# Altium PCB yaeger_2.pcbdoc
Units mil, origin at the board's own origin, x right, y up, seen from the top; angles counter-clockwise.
Board outline 3740.2 x 3149.6 mil, 2 copper layers (Top Layer, Bottom Layer), stack 62.2 mil thick; 33 components, 33 nets, 195 pads, 8 vias.
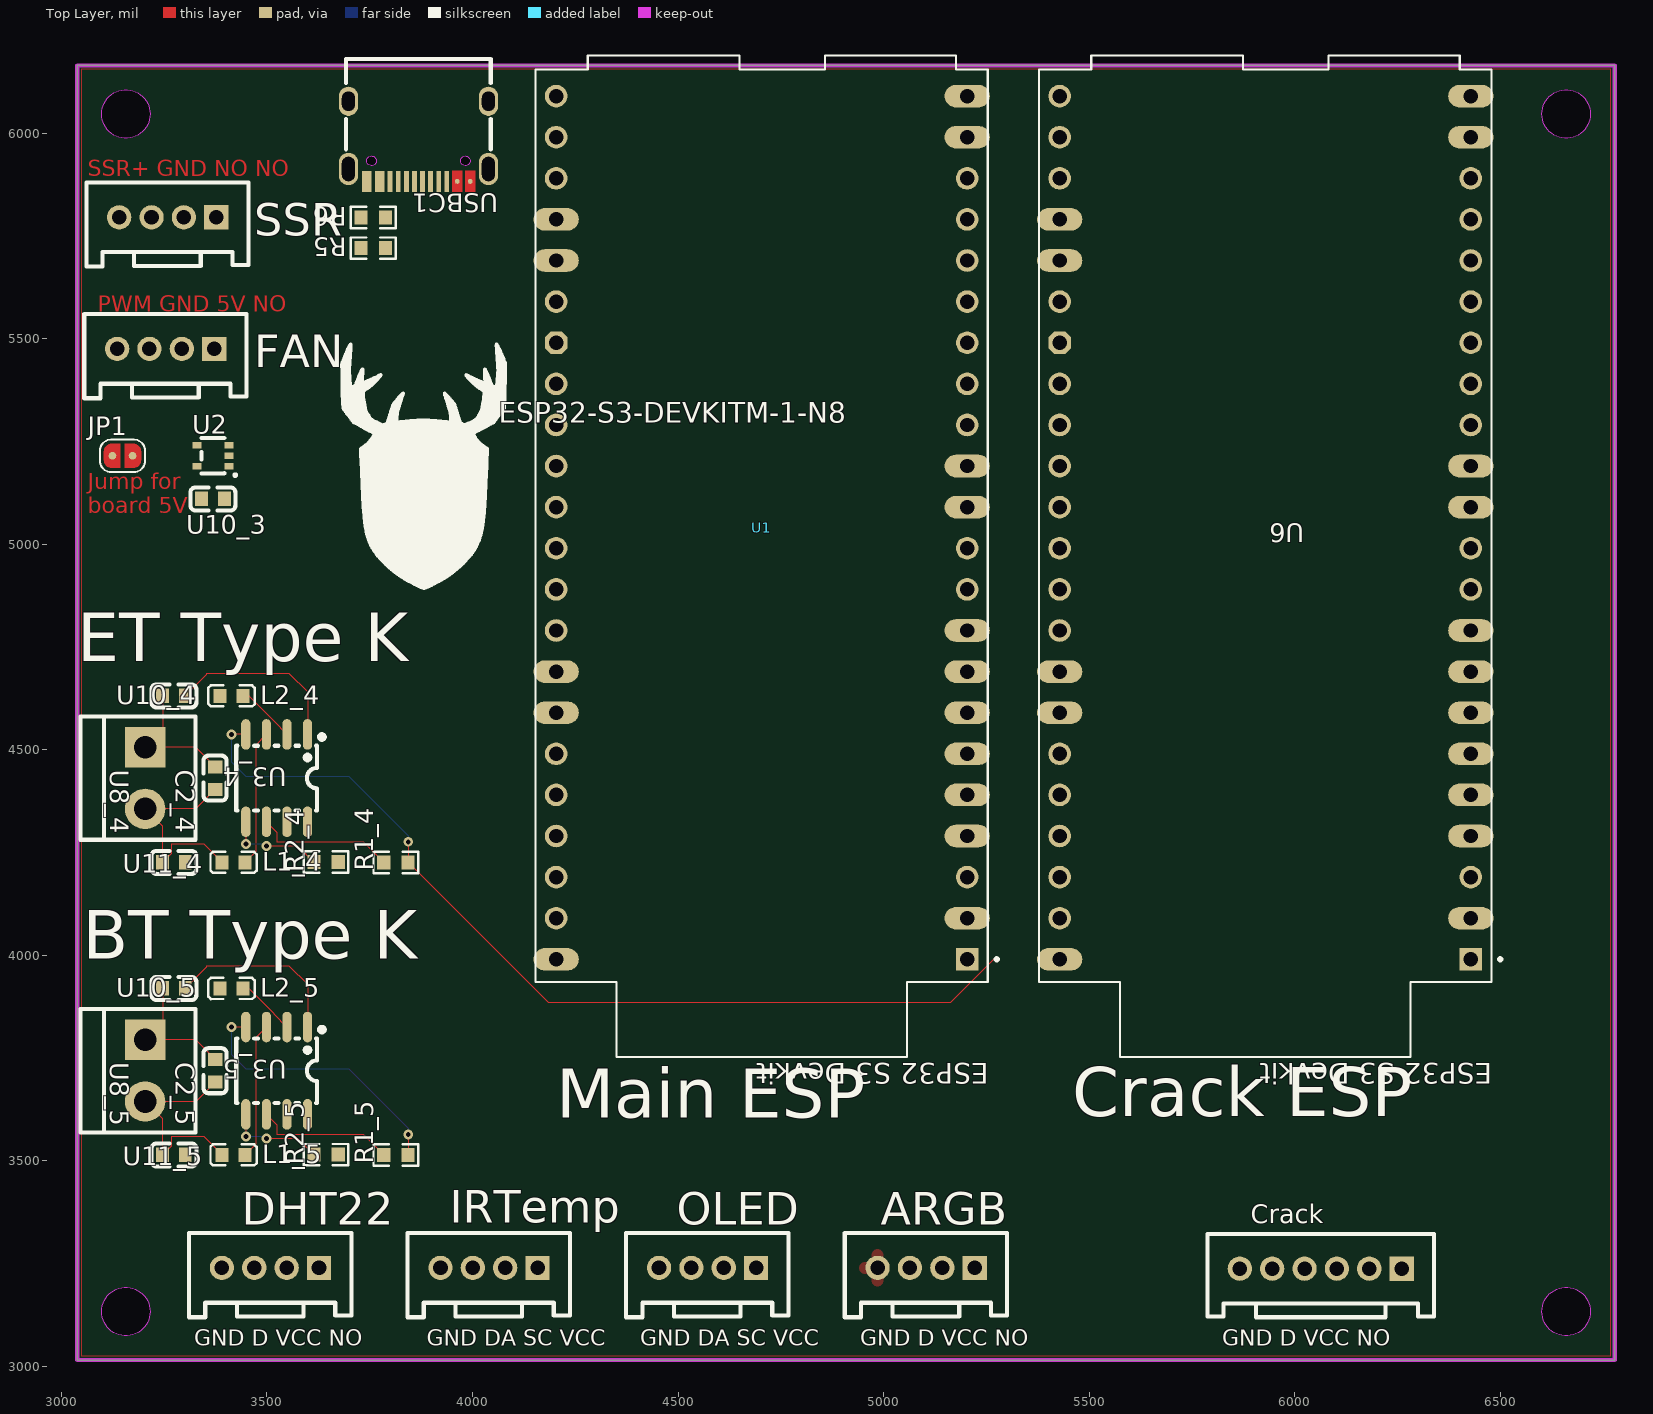
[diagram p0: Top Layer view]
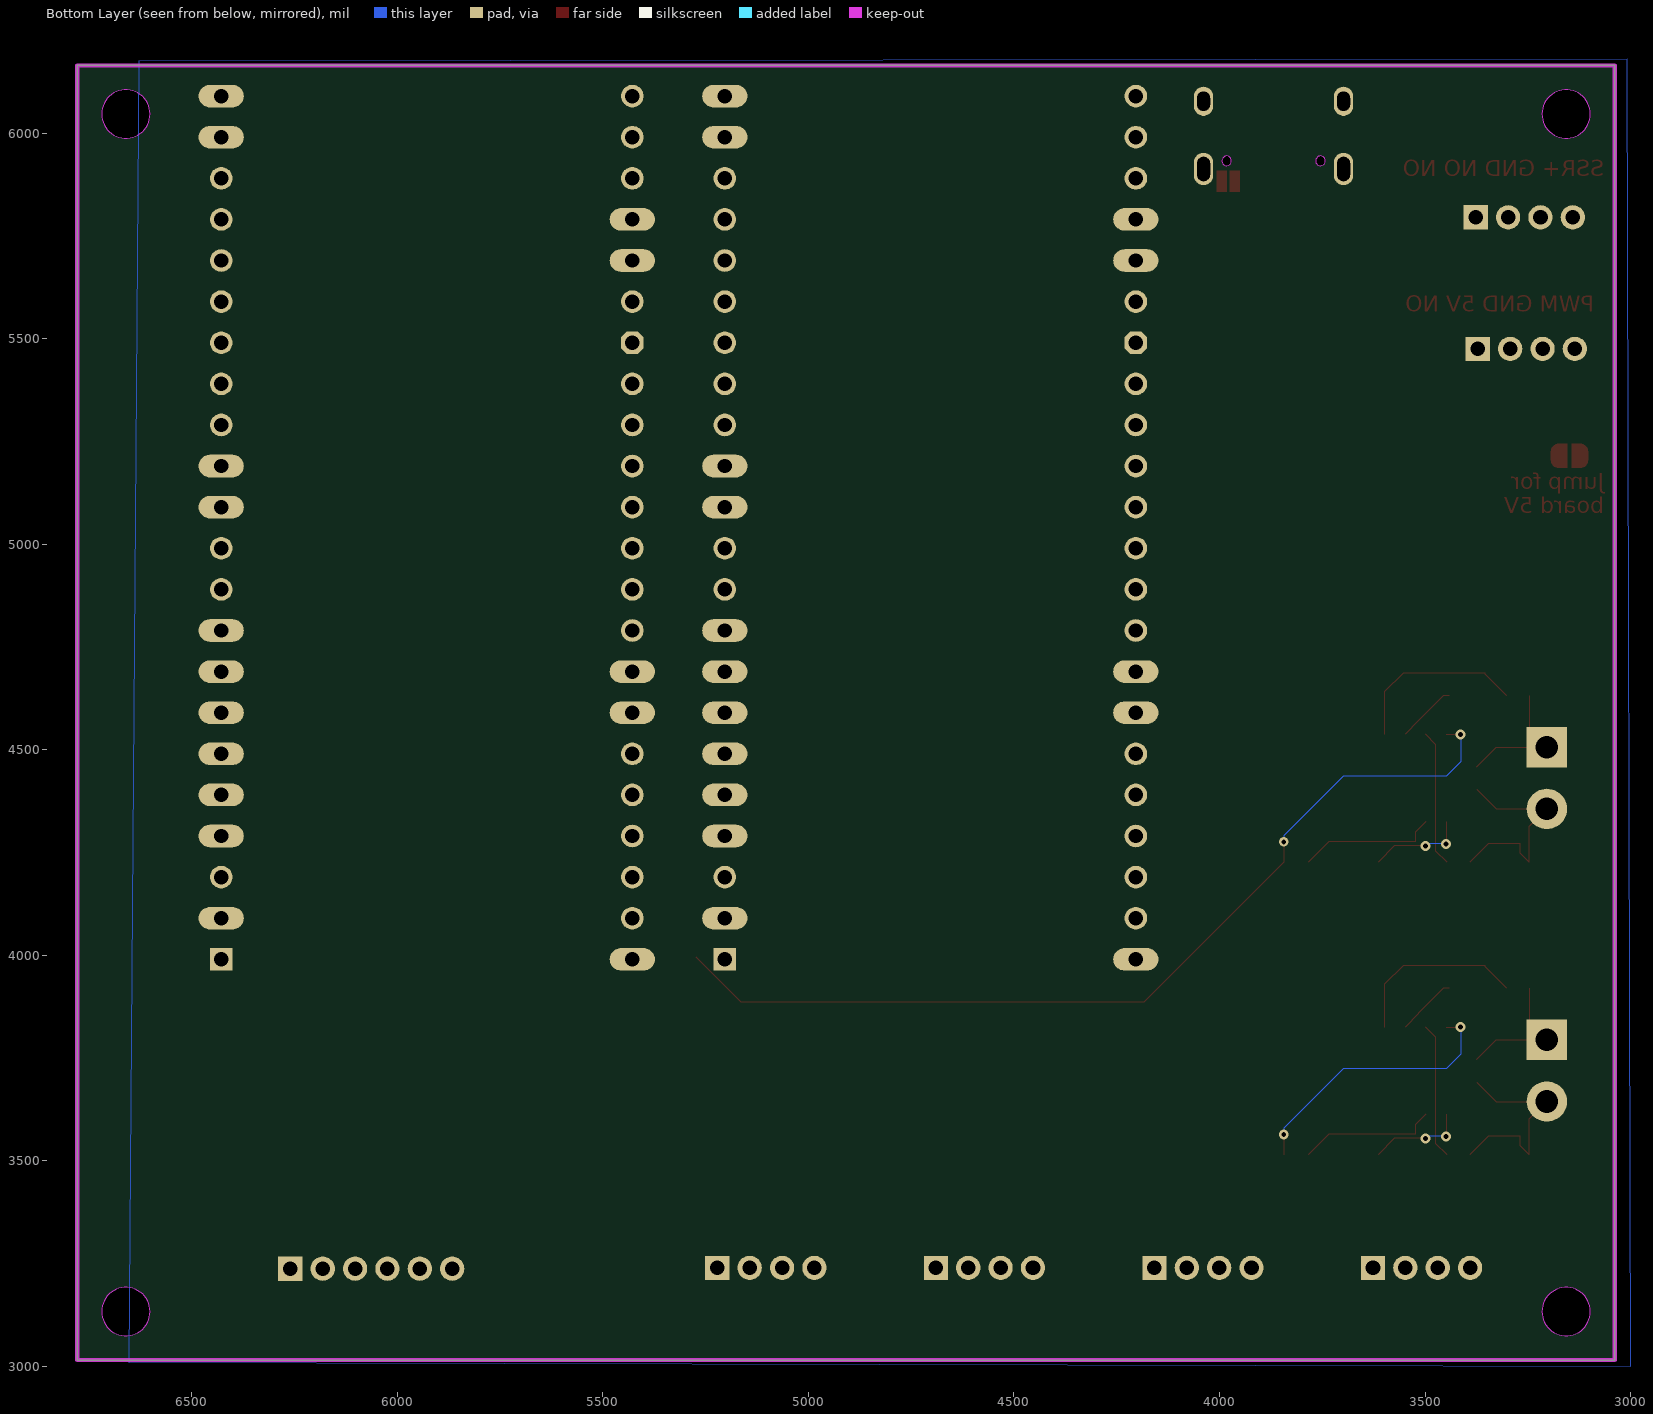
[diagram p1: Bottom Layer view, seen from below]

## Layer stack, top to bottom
Top Solder Mask Layer: solder mask 0.4, Dk 3.3
Top Layer: signal copper 1.4
Dielectric1: surface 59.4, FR4, Dk 4.5
Bottom Layer: signal copper 1.4
Bottom Solder Mask Layer: solder mask 0.4, Dk 3.3

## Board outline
3038.6,6164.7 3038.6,3015.1 6778.8,3015.1 6778.8,6164.7
cut-out: 3215.8,6046.6 3215.4,6039.7 3214.2,6032.9 3212.2,6026.4 3209.5,6020.1 3206.1,6014.1 3202,6008.6 3197.2,6003.6 3192,5999.2 3186.2,5995.4 3180.1,5992.3 3173.6,5990 3167,5988.4 3160.1,5987.6 3153.3,5987.6 3146.5,5988.4 3139.8,5990 3133.3,5992.3 3127.2,5995.4 3121.4,5999.2 3116.2,6003.6 3111.5,6008.6 3107.4,6014.1 3103.9,6020.1 3101.2,6026.4 3099.2,6032.9 3098.1,6039.7 3097.7,6046.6 3098.1,6053.4 3099.2,6060.2 3101.2,6066.8 3103.9,6073.1 3107.4,6079 3111.5,6084.5 3116.2,6089.5 3121.4,6093.9 3127.2,6097.7 3133.3,6100.8 3139.8,6103.1 3146.5,6104.7 3153.3,6105.5 3160.1,6105.5 3167,6104.7 3173.6,6103.1 3180.1,6100.8 3186.2,6097.7 3192,6093.9 3197.2,6089.5 3202,6084.5 3206.1,6079 3209.5,6073.1 3212.2,6066.8 3214.2,6060.2 3215.4,6053.4
cut-out: 6719.7,6046.6 6719.3,6039.7 6718.1,6032.9 6716.1,6026.4 6713.4,6020.1 6710,6014.1 6705.9,6008.6 6701.2,6003.6 6695.9,5999.2 6690.2,5995.4 6684,5992.3 6677.6,5990 6670.9,5988.4 6664.1,5987.6 6657.2,5987.6 6650.4,5988.4 6643.7,5990 6637.3,5992.3 6631.1,5995.4 6625.4,5999.2 6620.1,6003.6 6615.4,6008.6 6611.3,6014.1 6607.9,6020.1 6605.2,6026.4 6603.2,6032.9 6602,6039.7 6601.6,6046.6 6602,6053.4 6603.2,6060.2 6605.2,6066.8 6607.9,6073.1 6611.3,6079 6615.4,6084.5 6620.1,6089.5 6625.4,6093.9 6631.1,6097.7 6637.3,6100.8 6643.7,6103.1 6650.4,6104.7 6657.2,6105.5 6664.1,6105.5 6670.9,6104.7 6677.6,6103.1 6684,6100.8 6690.2,6097.7 6695.9,6093.9 6701.2,6089.5 6705.9,6084.5 6710,6079 6713.4,6073.1 6716.1,6066.8 6718.1,6060.2 6719.3,6053.4
cut-out: 6719.7,3133.2 6719.3,3126.3 6718.1,3119.6 6716.1,3113 6713.4,3106.7 6710,3100.7 6705.9,3095.2 6701.2,3090.2 6695.9,3085.8 6690.2,3082 6684,3078.9 6677.6,3076.6 6670.9,3075 6664.1,3074.2 6657.2,3074.2 6650.4,3075 6643.7,3076.6 6637.3,3078.9 6631.1,3082 6625.4,3085.8 6620.1,3090.2 6615.4,3095.2 6611.3,3100.7 6607.9,3106.7 6605.2,3113 6603.2,3119.6 6602,3126.3 6601.6,3133.2 6602,3140 6603.2,3146.8 6605.2,3153.4 6607.9,3159.7 6611.3,3165.6 6615.4,3171.1 6620.1,3176.1 6625.4,3180.5 6631.1,3184.3 6637.3,3187.4 6643.7,3189.7 6650.4,3191.3 6657.2,3192.1 6664.1,3192.1 6670.9,3191.3 6677.6,3189.7 6684,3187.4 6690.2,3184.3 6695.9,3180.5 6701.2,3176.1 6705.9,3171.1 6710,3165.6 6713.4,3159.7 6716.1,3153.4 6718.1,3146.8 6719.3,3140
cut-out: 3215.8,3133.2 3215.4,3126.3 3214.2,3119.6 3212.2,3113 3209.5,3106.7 3206.1,3100.7 3202,3095.2 3197.2,3090.2 3192,3085.8 3186.2,3082 3180.1,3078.9 3173.6,3076.6 3167,3075 3160.1,3074.2 3153.3,3074.2 3146.5,3075 3139.8,3076.6 3133.3,3078.9 3127.2,3082 3121.4,3085.8 3116.2,3090.2 3111.5,3095.2 3107.4,3100.7 3103.9,3106.7 3101.2,3113 3099.2,3119.6 3098.1,3126.3 3097.7,3133.2 3098.1,3140 3099.2,3146.8 3101.2,3153.4 3103.9,3159.7 3107.4,3165.6 3111.5,3171.1 3116.2,3176.1 3121.4,3180.5 3127.2,3184.3 3133.3,3187.4 3139.8,3189.7 3146.5,3191.3 3153.3,3192.1 3160.1,3192.1 3167,3191.3 3173.6,3189.7 3180.1,3187.4 3186.2,3184.3 3192,3180.5 3197.2,3176.1 3202,3171.1 3206.1,3165.6 3209.5,3159.7 3212.2,3153.4 3214.2,3146.8 3215.4,3140

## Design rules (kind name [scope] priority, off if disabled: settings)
BoardOutlineClearance safeClearance [All] p0: genericclearance=10 ignorepadtopadclearanceinfootprint=FALSE except(0: Arc-SplitContinuation Track-SplitContinuation SMDPad-SplitContinuation THPad-SplitContinuation Via-SplitContinuation Fill-SplitContinuation Poly-SplitContinuation Region-SplitContinuation Text-SplitContinuation)
BoardOutlineClearance Plane_innerPlane [All] p0: genericclearance=10 ignorepadtopadclearanceinfootprint=FALSE except(0: Arc-SplitContinuation Track-SplitContinuation SMDPad-SplitContinuation THPad-SplitContinuation Via-SplitContinuation Fill-SplitContinuation Poly-SplitContinuation Region-SplitContinuation Text-SplitContinuation)
BoardOutlineClearance Copper_CopperRegion [All] p0: genericclearance=10 ignorepadtopadclearanceinfootprint=FALSE except(0: Arc-SplitContinuation Track-SplitContinuation SMDPad-SplitContinuation THPad-SplitContinuation Via-SplitContinuation Fill-SplitContinuation Poly-SplitContinuation Region-SplitContinuation Text-SplitContinuation)
BoardOutlineClearance Copper_CopperRegion1 [All] p0: genericclearance=10 ignorepadtopadclearanceinfootprint=FALSE except(0: Arc-SplitContinuation Track-SplitContinuation SMDPad-SplitContinuation THPad-SplitContinuation Via-SplitContinuation Fill-SplitContinuation Poly-SplitContinuation Region-SplitContinuation Text-SplitContinuation)
BoardOutlineClearance otherClearance [All] p0: genericclearance=10 ignorepadtopadclearanceinfootprint=FALSE except(0: Arc-SplitContinuation Track-SplitContinuation SMDPad-SplitContinuation THPad-SplitContinuation Via-SplitContinuation Fill-SplitContinuation Poly-SplitContinuation Region-SplitContinuation Text-SplitContinuation)
Clearance safeClearance [All] p1: gap=7 ignorepadtopadclearanceinfootprint=FALSE
Clearance Plane_innerPlane [All] p1: gap=7 ignorepadtopadclearanceinfootprint=FALSE
Clearance Copper_CopperRegion [All] p1: gap=7 ignorepadtopadclearanceinfootprint=FALSE
Clearance Copper_CopperRegion1 [All] p1: gap=7 ignorepadtopadclearanceinfootprint=FALSE
Clearance otherClearance [All] p1: gap=7 ignorepadtopadclearanceinfootprint=FALSE
DiffPairsRouting differentialPair [All] p1: maxuncoupledlength=10 minlimit=6 maxlimit=Infinity mostfreqgap=6 toplayer_minwidth=5 toplayer_prefwidth=10 toplayer_maxwidth=100 bottomlayer_minwidth=5 bottomlayer_prefwidth=10 bottomlayer_maxwidth=100
PasteMaskExpansion Common [All] p1: expansion=0
PlaneConnect innerPlane [All] p1: planeconnectstyle=Relief reliefexpansion=20 reliefentries=4 reliefconductorwidth=10 reliefairgap=10
PolygonConnect CopperRegion [All] p1: connectstyle=Relief reliefentries=4 reliefconductorwidth=0 polygonreliefangle="90 Angle" airgapwidth=1
PolygonConnect CopperRegion1 [All] p1: connectstyle=Relief reliefentries=4 reliefconductorwidth=0 polygonreliefangle="90 Angle" airgapwidth=1
RoutingVias viaSize [All] p1: viastyle="Through Hole" holewidth=13.7796 minholewidth=13.7796 maxholewidth=78.7402 width=13.7796 minwidth=13.7796 maxwidth=78.7402
RoutingVias default [All] p1: viastyle="Through Hole" holewidth=12.0078 minholewidth=11.811 maxholewidth=248.0316 width=12.0078 minwidth=11.811 maxwidth=248.0316
SolderMaskExpansion Common [All] p1: useseparateexpansions=TRUE expansion=0 expansionbottom=0
Width trackWidth [All] p1: maxlimit=100 minlimit=8 preferedwidth=8
Width default [All] p1: maxlimit=100 minlimit=0 preferedwidth=0

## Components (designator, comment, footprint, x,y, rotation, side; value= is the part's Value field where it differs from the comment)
ARGB "HC-HY-4A" CONN-TH_4P-P2.00_HCTL_HC-HY-4A#1 5103.6,3239.4 r0 top
C2_4 "10nF" C0603#1 3373.7,4431 r270 top
C2_5 "10nF" C0603#1 3373.7,3719.2 r270 top
Crack "XD-HY-6A" CONN-TH_6P-P2.00_HCTL_HC-HY-6A 6063.6,3237.5 r180 top
DHT22 "HC-HY-4A" CONN-TH_4P-P2.00_HCTL_HC-HY-4A#1 3508.6,3239.4 r0 top
FAN "HC-HY-4A" CONN-TH_4P-P2.00_HCTL_HC-HY-4A#1 3253.6,5475.1 r0 top
IRTemp "HC-HY-4A" CONN-TH_4P-P2.00_HCTL_HC-HY-4A#2 4040.3,3239.4 r0 top
JP1 "Jumper_SolderJumper_2_Open" Jumper:SolderJumper-2_P1.3mm_Open_RoundedPad1.0x1.5mm 3148.6,5215.1 r0 top
L1_4 "BLM18AG601SN1D" L0603 3418.7,4226 r0 top
L1_5 "BLM18AG601SN1D" L0603 3418.7,3514.2 r0 top
L2_4 "BLM18AG601SN1D" L0603 3413.7,4631 r0 top
L2_5 "BLM18AG601SN1D" L0603 3413.7,3919.2 r0 top
OLED "HC-HY-4A" CONN-TH_4P-P2.00_HCTL_HC-HY-4A#3 4571.9,3239.4 r0 top
R1_4 "10kΩ" R0603#1 3813.7,4226 r0 top
R1_5 "10kΩ" R0603#1 3813.7,3514.2 r0 top
R2_4 "10kΩ" R0603#1 3643.7,4226.7 r0 top
R2_5 "10kΩ" R0603#1 3643.7,3514.8 r0 top
R5 "5.1kΩ" R0603#2 3758.6,5720.1 r180 top
R6 "5.1kΩ" R0603#2 3758.6,5795.1 r180 top
SSR "HC-HY-4A" CONN-TH_4P-P2.00_HCTL_HC-HY-4A#1 3258.6,5795.1 r0 top
U1 "ESP32-S3-DEVKITM-1-N8" MODULE_ESP32-S3-DEVKITM-1-N8 4753.6,5170.1 r180 top
U2 "74AHCT1G125GW/C2125" TSSOP-5_L2.1-W1.3-P0.65-LS2.2-BR 3368.6,5215.1 r0 top
U3_4 "MAX31855KASA+T" SO-8_L4.9-W3.9-P1.27-LS5.9-BL 3523.7,4431 r180 top
U3_5 "MAX31855KASA+T" SO-8_L4.9-W3.9-P1.27-LS5.9-BL 3523.7,3719.2 r180 top
U6 "ESP32-S3-DEVKITM-1-N8" MODULE_ESP32-S3-DEVKITM-1-N8 5978.6,5170.1 r180 top
U8_4 "XY340V-3.81-2P" CONN-TH_XY340V-3.81-2P 3203.7,4431 r270 top
U8_5 "XY340V-3.81-2P" CONN-TH_XY340V-3.81-2P 3203.7,3719.2 r270 top
U10_3 "100nF" C0603#2 3368.6,5110.1 r0 top
U10_4 "100nF" C0603#1 3273.7,4631 r0 top
U10_5 "100nF" C0603#1 3273.7,3919.2 r0 top
U11_4 "100nF" C0603#1 3273.7,4226 r0 top
U11_5 "100nF" C0603#1 3273.7,3514.2 r0 top
USBC1 "TYPE-C-31-M-12" USB-C_SMD-TYPE-C-31-M-12_1 3868.6,5980.1 r180 top

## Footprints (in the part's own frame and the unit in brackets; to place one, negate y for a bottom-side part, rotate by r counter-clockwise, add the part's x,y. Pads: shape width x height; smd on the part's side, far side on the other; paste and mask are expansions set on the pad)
C0603#1 [mil]
  rect 31.5x35.4 smd: 1(-27.5,0) 2(27.6,0)
  silkscreen extent -55,-28 55,28
C0603#2 [mil]
  rect 31.5x35.4 smd: 1(-27.6,0) 2(27.6,0)
  silkscreen extent -55,-28 55,28
CONN-TH_4P-P2.00_HCTL_HC-HY-4A#1 [mil]
  rect 59.1x59.1 hole 35.4 paste+0 mask+2: 1(118.1,0)
  round 59.1 hole 35.4 paste+0 mask+2: 2(39.4,0) 3(-39.4,0) 4(-118.1,0)
  silkscreen extent -198,-120 197,85
CONN-TH_4P-P2.00_HCTL_HC-HY-4A#2 [mil]
  rect 59.1x59.1 hole 35.4 paste+0 mask+2: 1(118.1,0)
  round 59.1 hole 35.4 paste+0 mask+2: 2(39.3,0) 3(-39.4,0) 4(-118.1,0)
  silkscreen extent -198,-120 197,85
CONN-TH_4P-P2.00_HCTL_HC-HY-4A#3 [mil]
  rect 59.1x59.1 hole 35.4 paste+0 mask+2: 1(118.1,0)
  round 59.1 hole 35.4 paste+0 mask+2: 2(39.4,0) 3(-39.3,0) 4(-118.1,0)
  silkscreen extent -198,-120 197,85
CONN-TH_6P-P2.00_HCTL_HC-HY-6A [mil]
  rect 59.1x59.1 hole 35.4 paste+0 mask+2: 1(-196.9,0)
  round 59.1 hole 35.4 paste+0 mask+2: 2(-118.1,0) 3(-39.4,0) 4(39.4,0) 5(118.1,0) 6(196.8,0)
  silkscreen extent -276,-85 276,118
CONN-TH_XY340V-3.81-2P [mil]
  rect 98.4x98.4 hole 55.1: 1(-75,0)
  round 98.4 hole 55.1: 2(75,0)
  silkscreen extent -150,-158 150,122
Jumper:SolderJumper-2_P1.3mm_Open_RoundedPad1.0x1.5mm [mil]
  round 18.5 smd: 1(-24.4,0) 2(24.4,0)
  Top Layer region: -5.9,9.8 -5.9,29.5 -25.6,29.5 -29.4,29.1 -33.1,28 -36.5,26.2 -39.5,23.7 -42,20.7 -43.8,17.3 -44.9,13.6 -45.3,9.8 -45.3,-9.9 -44.9,-13.7 -43.8,-17.4 -42,-20.8 -39.5,-23.8 -36.5,-26.2 -33.1,-28.1 -29.4,-29.2 -25.6,-29.6 -5.9,-29.6 -5.9,-9.9
  Top Layer region: 5.9,29.5 5.9,9.8 5.9,-9.9 5.9,-29.6 25.6,-29.6 29.4,-29.2 33.1,-28.1 36.5,-26.2 39.5,-23.8 42,-20.8 43.8,-17.4 44.9,-13.7 45.3,-9.9 45.3,9.8 44.9,13.6 43.8,17.3 42,20.7 39.5,23.7 36.5,26.2 33.1,28 29.4,29.1 25.6,29.5
  silkscreen extent -55,-39 55,39
L0603 [mil]
  rect 31.5x34 smd paste-3937 mask+2: 1(-27.5,0) 2(27.6,0)
  silkscreen extent -56,-26 56,26
MODULE_ESP32-S3-DEVKITM-1-N8 [mil]
  rect 55x55 hole 35 paste+0 mask+4: J11(-450,1180)
  oval 110x55 hole 35 paste+0 mask+4: J12(-450,1080) J14(-450,880) J15(-450,780) J16(-450,680) J17(-450,580) J18(-450,480) J19(-450,380) J31(550,1180) J37(550,580) J38(550,480) J112(-450,80) J113(-450,-20) J121(-450,-820) J122(-450,-920) J318(550,-520) J319(550,-620)
  round 55 hole 35 paste+0 mask+4: J13(-450,980) J32(550,1080) J33(550,980) J34(550,880) J35(550,780) J36(550,680) J39(550,380) J110(-450,280) J111(-450,180) J114(-450,-120) J115(-450,-220) J116(-450,-320) J117(-450,-420) J118(-450,-520) J119(-450,-620) J120(-450,-720) J310(550,280) J311(550,180) J312(550,80) J313(550,-20) J314(550,-120) J315(550,-220) J317(550,-420) J320(550,-720) J321(550,-820) J322(550,-920)
  oct 55x55 hole 35 paste+0 mask+4: J316(550,-320)
  silkscreen extent -526,-1019 600,1418
R0603#1 [mil]
  rect 31.8x34 smd paste-3937 mask+2: 1(-29.6,0) 2(29.7,0)
  silkscreen extent -54,-26 55,26
R0603#2 [mil]
  rect 31.8x34 smd paste-3937 mask+2: 1(-29.7,0) 2(29.7,0)
  silkscreen extent -54,-26 54,26
SO-8_L4.9-W3.9-P1.27-LS5.9-BL [mil]
  oval 22.6x74.3 smd: 1(-75,-106.2) 2(-25,-106.2) 3(25,-106.2) 4(75,-106.2) 5(75,106.3) 6(25,106.3) 7(-25,106.3) 8(-75,106.3)
  silkscreen extent -116,-106 98,79
TSSOP-5_L2.1-W1.3-P0.65-LS2.2-BR [mil]
  rect 21.7x15.7 smd paste+0 mask+2: 1(39,-25) 2(39,0) 3(39,26) 4(-39,26) 5(-39,-26)
  silkscreen extent -28,-49 56,43
USB-C_SMD-TYPE-C-31-M-12_1 [mil]
  oval 47.2x78.7 hole 31.5 slot 59.1 at 90 deg paste+0 mask+2: 1(170.3,67.2) 4(-170.3,67.2)
  oval 47.2x70.9 hole 31.5 slot 47.2 at 90 deg paste+0 mask+2: 2(170.3,-97.4) 3(-170.3,-97.4)
  round 11.8 smd: A1B12(-126,97.4) A4B9(-94.5,97.4)
  rect 11.8x51.2 smd paste-3937 mask+2: A5(-49.2,97.4) A6(-9.8,97.4) A7(9.8,97.4) A8(49.2,97.4) B5(68.9,97.4) B6(29.5,97.4) B7(-29.5,97.4) B8(-68.9,97.4)
  rect 23.6x51.2 smd paste-3937 mask+2: B1A12(126,97.4) B4A9(94.5,97.4)
  Top Layer region: -114.2,71.9 -114.2,123 -126,123 -126,123 -137.8,123 -137.8,71.8 -126,71.8 -126,71.9
  Top Layer region: -82.7,71.8 -82.7,123 -94.5,123 -94.5,123 -106.3,123 -106.3,71.8 -94.5,71.8 -94.5,71.8
  Board Outline Layer lines w0.1: 126,47.5 125.6,44.6 124.5,41.8 122.8,39.4 120.5,37.5 117.8,36.3 114.9,35.7 112,35.9 109.1,36.8 106.6,38.4 104.6,40.6 103.2,43.2 102.5,46 102.5,49 103.2,51.8 104.6,54.4 106.6,56.6 109.1,58.2 112,59.1 114.9,59.3 117.8,58.7 120.5,57.5 122.8,55.6 124.5,53.2 125.6,50.4 126,47.5 ; -102.4,47.5 -102.7,44.6 -103.8,41.8 -105.6,39.4 -107.8,37.5 -110.5,36.3 -113.4,35.7 -116.4,35.9 -119.2,36.8 -121.7,38.4 -123.7,40.6 -125.2,43.2 -125.9,46 -125.9,49 -125.2,51.8 -123.7,54.4 -121.7,56.6 -119.2,58.2 -116.4,59.1 -113.4,59.3 -110.5,58.7 -107.8,57.5 -105.6,55.6 -103.8,53.2 -102.7,50.4 -102.4,47.5
  Board Outline Layer region: -102.4,47.5 -102.7,44.6 -103.8,41.8 -105.6,39.4 -107.8,37.5 -110.5,36.3 -113.4,35.7 -116.4,35.9 -119.2,36.8 -121.7,38.4 -123.7,40.6 -125.2,43.2 -125.9,46 -125.9,49 -125.2,51.8 -123.7,54.4 -121.7,56.6 -119.2,58.2 -116.4,59.1 -113.4,59.3 -110.5,58.7 -107.8,57.5 -105.6,55.6 -103.8,53.2 -102.7,50.4
  Board Outline Layer region: -102.4,47.5 -102.7,44.6 -103.8,41.8 -105.6,39.4 -107.8,37.5 -110.5,36.3 -113.4,35.7 -116.4,35.9 -119.2,36.8 -121.7,38.4 -123.7,40.6 -125.2,43.2 -125.9,46 -125.9,49 -125.2,51.8 -123.7,54.4 -121.7,56.6 -119.2,58.2 -116.4,59.1 -113.4,59.3 -110.5,58.7 -107.8,57.5 -105.6,55.6 -103.8,53.2 -102.7,50.4
  Board Outline Layer region: 126,47.5 125.6,44.6 124.5,41.8 122.8,39.4 120.5,37.5 117.8,36.3 114.9,35.7 112,35.9 109.1,36.8 106.6,38.4 104.6,40.6 103.2,43.2 102.5,46 102.5,49 103.2,51.8 104.6,54.4 106.6,56.6 109.1,58.2 112,59.1 114.9,59.3 117.8,58.7 120.5,57.5 122.8,55.6 124.5,53.2 125.6,50.4
  Board Outline Layer region: 126,47.5 125.6,44.6 124.5,41.8 122.8,39.4 120.5,37.5 117.8,36.3 114.9,35.7 112,35.9 109.1,36.8 106.6,38.4 104.6,40.6 103.2,43.2 102.5,46 102.5,49 103.2,51.8 104.6,54.4 106.6,56.6 109.1,58.2 112,59.1 114.9,59.3 117.8,58.7 120.5,57.5 122.8,55.6 124.5,53.2 125.6,50.4
  Multi-Layer board cut-out: -102.4,47.5 -102.7,44.6 -103.8,41.8 -105.6,39.4 -107.8,37.5 -110.5,36.3 -113.4,35.7 -116.4,35.9 -119.2,36.8 -121.7,38.4 -123.7,40.6 -125.2,43.2 -125.9,46 -125.9,49 -125.2,51.8 -123.7,54.4 -121.7,56.6 -119.2,58.2 -116.4,59.1 -113.4,59.3 -110.5,58.7 -107.8,57.5 -105.6,55.6 -103.8,53.2 -102.7,50.4
  Multi-Layer board cut-out: 126,47.5 125.6,44.6 124.5,41.8 122.8,39.4 120.5,37.5 117.8,36.3 114.9,35.7 112,35.9 109.1,36.8 106.6,38.4 104.6,40.6 103.2,43.2 102.5,46 102.5,49 103.2,51.8 104.6,54.4 106.6,56.6 109.1,58.2 112,59.1 114.9,59.3 117.8,58.7 120.5,57.5 122.8,55.6 124.5,53.2 125.6,50.4
  silkscreen extent -176,-201 176,19

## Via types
v1: diameter 24, hole 12, Top Layer to Bottom Layer, 8 vias

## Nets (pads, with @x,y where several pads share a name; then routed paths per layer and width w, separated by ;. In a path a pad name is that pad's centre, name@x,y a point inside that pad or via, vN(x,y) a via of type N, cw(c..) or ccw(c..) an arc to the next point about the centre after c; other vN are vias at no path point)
$1N209: U1.J111 U6.J32
$1N210: U1.J110 U6.J33
$1N212: DHT22.3 U1.J17
$1N218: Crack.1 U6.J120
$1N220: Crack.3 U6.J119
$1N221: Crack.2 U6.J18
$1N222: Crack.4 U6.J11
$1N223: Crack.5 Crack.6 U6.J31
$1N277: R5.1 USBC1.A5
$1N278: R6.1 USBC1.B5
$1N314: FAN.3 U2.4
$1N321: FAN.2 JP1.1
$1N330: C2_4.2 L1_4.1 U8_4.2 U11_4.1 | length 532.6
  Top Layer w0.1: 3268.7,4271 3268.7,4248.5 U11_4.1 3246.2,4313.5 U8_4.2 3326.3,4356 C2_4.2 ; 3268.8,4271 3346.1,4271 L1_4.1
$1N331: C2_4.1 L2_4.1 U8_4.1 U10_4.1 | length 332.3
  Top Layer w0.1: U10_4.1 3246.2,4548.4 U8_4.1 3326.3,4506 C2_4.1
$1N334: L1_4.2 U3_4.3 | length 332.9
  Top Layer w0.1: L1_4.2 3473.7,4253.4 3473.7,4512.2 U3_4.3
$1N335: L2_4.2 U3_4.2 | length 146.5
  Top Layer w0.1: L2_4.2 3455.4,4631 3516.1,4570.3 3516.1,4569.9 U3_4.2
$1N345: C2_5.2 L1_5.1 U8_5.2 U11_5.1 | length 532.6
  Top Layer w0.1: 3268.7,3559.2 3268.7,3536.7 U11_5.1 3246.2,3601.7 U8_5.2 3326.3,3644.2 C2_5.2 ; 3268.8,3559.2 3346.1,3559.2 L1_5.1
$1N346: C2_5.1 L2_5.1 U8_5.1 U10_5.1 | length 332.3
  Top Layer w0.1: U10_5.1 3246.2,3836.6 U8_5.1 3326.3,3794.2 C2_5.1
$1N349: L1_5.2 U3_5.3 | length 332.9
  Top Layer w0.1: L1_5.2 3473.7,3541.6 3473.7,3800.4 U3_5.3
$1N350: L2_5.2 U3_5.2 | length 146.5
  Top Layer w0.1: L2_5.2 3455.4,3919.2 3516.1,3858.5 3516.1,3858.1 U3_5.2
+5V: ARGB.2 U1.J121 U6.J121 USBC1.A4B9 USBC1.B4A9
CS1: R1_4.1 R1_5.1 U1.J18 U1.J19 U3_4.6 U3_5.6 | length 680
  Top Layer w0.1: U3_5.6 3523.7,3587.9 3523.7,3564.2 ; U3_4.6 3523.7,4299.7 3523.7,4276 ; 3523.8,3564.1 3734.1,3564.1 R1_5.1 ; 3523.8,4275.9 3734.1,4275.9 R1_4.1
DA: IRTemp.3 OLED.3 U1.J37
FAN: U1.J112 U2.2
GND: ARGB.4 DHT22.4 FAN.4 IRTemp.4 OLED.4 R2_4.2 R2_5.2 R5.2 R6.2 SSR.4 U1.J31 U1.J122 U1.J321 U1.J322 U2.1 U2.3 U3_4.1 U3_5.1 U6.J122 U6.J321 U10_3.2 U10_4.2 U10_5.2 U11_4.2 U11_5.2 USBC1.1 USBC1.2 USBC1.3 USBC1.4 USBC1.A1B12 USBC1.A8 USBC1.B1A12 USBC1.B8 | length 888
  Top Layer w0.1: U10_5.2 3353.7,3971.6 3353.7,3974.2 ; U10_4.2 3353.7,4683.4 3353.7,4686 ; 3353.8,3974.2 3553.6,3974.2 3598.7,3929.2 U3_5.1 ; 3353.8,4686 3553.6,4686 3598.7,4641 U3_4.1
N$1: ARGB.3 U1.J14
N$4: U1.J320 USBC1.A7 USBC1.B7
N$7: U1.J319 USBC1.A6 USBC1.B6
SC: IRTemp.2 OLED.2 U1.J36
SCK: R2_4.1 R2_5.1 U1.J16 U3_4.5 U3_5.5 | length 474.9
  Top Layer w0.1: v1(3448.7,3559.2) U3_5.5 ; v1(3448.7,4271) U3_4.5 ; v1(3498.7,3554.2) 3574.7,3554.2 R2_5.1 ; v1(3498.7,4266) 3574.7,4266 R2_4.1
  Bottom Layer w0.1: v1(3448.7,3559.2) 3493.7,3559.2 v1(3498.7,3554.2) ; v1(3448.7,4271) 3493.7,4271 v1(3498.7,4266)
SO: U1.J15 U3_4.7 U3_5.7
SSR: SSR.3 U1.J113
VCC: DHT22.2 IRTemp.1 JP1.2 OLED.1 R1_4.2 R1_5.2 U1.J11 U1.J12 U2.5 U3_4.4 U3_5.4 U10_3.1 | length 2958.7
  Top Layer w0.1: v1(3413.7,3825.4) U3_5.4 ; v1(3413.7,4537.2) U3_4.4 ; R1_5.2 3843.7,3514.5 v1(3843.7,3564.2) ; v1(3843.7,4276) 3843.7,4226.3 R1_4.2 4184.3,3885.1 5163.5,3885.1 5273.6,3995.1
  Bottom Layer w0.1: v1(3413.7,3825.4) 3413.7,3759.2 3448.7,3724.2 3698.7,3724.2 3843.7,3579.2 v1(3843.7,3564.2) ; v1(3413.7,4537.2) 3413.7,4471 3448.7,4436 3698.7,4436 3843.7,4291 v1(3843.7,4276)
pads on no net: ARGB.1 DHT22.1 FAN.1 SSR.1 SSR.2 U1.J13 U1.J32 U1.J33 U1.J34 U1.J35 U1.J38 U1.J39 U1.J114 U1.J115 U1.J116 U1.J117 U1.J118 U1.J119 U1.J120 U1.J310 U1.J311 U1.J312 U1.J313 U1.J314 U1.J315 U1.J316 U1.J317 U1.J318 U3_4.8 U3_5.8 U6.J12 U6.J13 U6.J14 U6.J15 U6.J16 U6.J17 U6.J19 U6.J34 U6.J35 U6.J36 U6.J37 U6.J38 U6.J39 U6.J110 U6.J111 U6.J112 U6.J113 U6.J114 U6.J115 U6.J116 U6.J117 U6.J118 U6.J310 U6.J311 U6.J312 U6.J313 U6.J314 U6.J315 U6.J316 U6.J317 U6.J318 U6.J319 U6.J320 U6.J322

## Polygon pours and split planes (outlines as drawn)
GND on Bottom Layer (solid, pour order 8): 3000,3000 3008.6,6180.2 6628.7,6174.7 6653.6,3010.1
GND on Top Layer (solid, remove dead copper, pour order 4): 3048.6,6155.1 3048.6,3025.1 6768.6,3025.1 6768.6,6155.1
GND on Top Layer (solid, remove dead copper, pour order 6): 3268.6,3445.1 3268.6,3035.1 5358.6,3035.1 5358.6,3445.1
GND on Top Layer (solid, pour order 8): 3038.7,4721 3038.7,4150.4 3989.9,4150.4 3989.9,4721
GND on Top Layer (solid, remove dead copper, pour order 10): 3038.7,4009.2 3038.7,3438.6 3989.9,3438.6 3989.9,4009.2

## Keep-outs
Board Outline Layer:
  region: 3215.8,6046.6 3215.4,6039.7 3214.2,6032.9 3212.2,6026.4 3209.5,6020.1 3206.1,6014.1 3202,6008.6 3197.2,6003.6 3192,5999.2 3186.2,5995.4 3180.1,5992.3 3173.6,5990 3167,5988.4 3160.1,5987.6 3153.3,5987.6 3146.5,5988.4 3139.8,5990 3133.3,5992.3 3127.2,5995.4 3121.4,5999.2 3116.2,6003.6 3111.5,6008.6 3107.4,6014.1 3103.9,6020.1 3101.2,6026.4 3099.2,6032.9 3098.1,6039.7 3097.7,6046.6 3098.1,6053.4 3099.2,6060.2 3101.2,6066.8 3103.9,6073.1 3107.4,6079 3111.5,6084.5 3116.2,6089.5 3121.4,6093.9 3127.2,6097.7 3133.3,6100.8 3139.8,6103.1 3146.5,6104.7 3153.3,6105.5 3160.1,6105.5 3167,6104.7 3173.6,6103.1 3180.1,6100.8 3186.2,6097.7 3192,6093.9 3197.2,6089.5 3202,6084.5 3206.1,6079 3209.5,6073.1 3212.2,6066.8 3214.2,6060.2 3215.4,6053.4
  region: 3215.8,6046.6 3215.4,6039.7 3214.2,6032.9 3212.2,6026.4 3209.5,6020.1 3206.1,6014.1 3202,6008.6 3197.2,6003.6 3192,5999.2 3186.2,5995.4 3180.1,5992.3 3173.6,5990 3167,5988.4 3160.1,5987.6 3153.3,5987.6 3146.5,5988.4 3139.8,5990 3133.3,5992.3 3127.2,5995.4 3121.4,5999.2 3116.2,6003.6 3111.5,6008.6 3107.4,6014.1 3103.9,6020.1 3101.2,6026.4 3099.2,6032.9 3098.1,6039.7 3097.7,6046.6 3098.1,6053.4 3099.2,6060.2 3101.2,6066.8 3103.9,6073.1 3107.4,6079 3111.5,6084.5 3116.2,6089.5 3121.4,6093.9 3127.2,6097.7 3133.3,6100.8 3139.8,6103.1 3146.5,6104.7 3153.3,6105.5 3160.1,6105.5 3167,6104.7 3173.6,6103.1 3180.1,6100.8 3186.2,6097.7 3192,6093.9 3197.2,6089.5 3202,6084.5 3206.1,6079 3209.5,6073.1 3212.2,6066.8 3214.2,6060.2 3215.4,6053.4
  region: 6719.7,6046.6 6719.3,6039.7 6718.1,6032.9 6716.1,6026.4 6713.4,6020.1 6710,6014.1 6705.9,6008.6 6701.2,6003.6 6695.9,5999.2 6690.2,5995.4 6684,5992.3 6677.6,5990 6670.9,5988.4 6664.1,5987.6 6657.2,5987.6 6650.4,5988.4 6643.7,5990 6637.3,5992.3 6631.1,5995.4 6625.4,5999.2 6620.1,6003.6 6615.4,6008.6 6611.3,6014.1 6607.9,6020.1 6605.2,6026.4 6603.2,6032.9 6602,6039.7 6601.6,6046.6 6602,6053.4 6603.2,6060.2 6605.2,6066.8 6607.9,6073.1 6611.3,6079 6615.4,6084.5 6620.1,6089.5 6625.4,6093.9 6631.1,6097.7 6637.3,6100.8 6643.7,6103.1 6650.4,6104.7 6657.2,6105.5 6664.1,6105.5 6670.9,6104.7 6677.6,6103.1 6684,6100.8 6690.2,6097.7 6695.9,6093.9 6701.2,6089.5 6705.9,6084.5 6710,6079 6713.4,6073.1 6716.1,6066.8 6718.1,6060.2 6719.3,6053.4
  region: 6719.7,6046.6 6719.3,6039.7 6718.1,6032.9 6716.1,6026.4 6713.4,6020.1 6710,6014.1 6705.9,6008.6 6701.2,6003.6 6695.9,5999.2 6690.2,5995.4 6684,5992.3 6677.6,5990 6670.9,5988.4 6664.1,5987.6 6657.2,5987.6 6650.4,5988.4 6643.7,5990 6637.3,5992.3 6631.1,5995.4 6625.4,5999.2 6620.1,6003.6 6615.4,6008.6 6611.3,6014.1 6607.9,6020.1 6605.2,6026.4 6603.2,6032.9 6602,6039.7 6601.6,6046.6 6602,6053.4 6603.2,6060.2 6605.2,6066.8 6607.9,6073.1 6611.3,6079 6615.4,6084.5 6620.1,6089.5 6625.4,6093.9 6631.1,6097.7 6637.3,6100.8 6643.7,6103.1 6650.4,6104.7 6657.2,6105.5 6664.1,6105.5 6670.9,6104.7 6677.6,6103.1 6684,6100.8 6690.2,6097.7 6695.9,6093.9 6701.2,6089.5 6705.9,6084.5 6710,6079 6713.4,6073.1 6716.1,6066.8 6718.1,6060.2 6719.3,6053.4
  region: 6719.7,3133.2 6719.3,3126.3 6718.1,3119.6 6716.1,3113 6713.4,3106.7 6710,3100.7 6705.9,3095.2 6701.2,3090.2 6695.9,3085.8 6690.2,3082 6684,3078.9 6677.6,3076.6 6670.9,3075 6664.1,3074.2 6657.2,3074.2 6650.4,3075 6643.7,3076.6 6637.3,3078.9 6631.1,3082 6625.4,3085.8 6620.1,3090.2 6615.4,3095.2 6611.3,3100.7 6607.9,3106.7 6605.2,3113 6603.2,3119.6 6602,3126.3 6601.6,3133.2 6602,3140 6603.2,3146.8 6605.2,3153.4 6607.9,3159.7 6611.3,3165.6 6615.4,3171.1 6620.1,3176.1 6625.4,3180.5 6631.1,3184.3 6637.3,3187.4 6643.7,3189.7 6650.4,3191.3 6657.2,3192.1 6664.1,3192.1 6670.9,3191.3 6677.6,3189.7 6684,3187.4 6690.2,3184.3 6695.9,3180.5 6701.2,3176.1 6705.9,3171.1 6710,3165.6 6713.4,3159.7 6716.1,3153.4 6718.1,3146.8 6719.3,3140
  region: 6719.7,3133.2 6719.3,3126.3 6718.1,3119.6 6716.1,3113 6713.4,3106.7 6710,3100.7 6705.9,3095.2 6701.2,3090.2 6695.9,3085.8 6690.2,3082 6684,3078.9 6677.6,3076.6 6670.9,3075 6664.1,3074.2 6657.2,3074.2 6650.4,3075 6643.7,3076.6 6637.3,3078.9 6631.1,3082 6625.4,3085.8 6620.1,3090.2 6615.4,3095.2 6611.3,3100.7 6607.9,3106.7 6605.2,3113 6603.2,3119.6 6602,3126.3 6601.6,3133.2 6602,3140 6603.2,3146.8 6605.2,3153.4 6607.9,3159.7 6611.3,3165.6 6615.4,3171.1 6620.1,3176.1 6625.4,3180.5 6631.1,3184.3 6637.3,3187.4 6643.7,3189.7 6650.4,3191.3 6657.2,3192.1 6664.1,3192.1 6670.9,3191.3 6677.6,3189.7 6684,3187.4 6690.2,3184.3 6695.9,3180.5 6701.2,3176.1 6705.9,3171.1 6710,3165.6 6713.4,3159.7 6716.1,3153.4 6718.1,3146.8 6719.3,3140
  region: 3215.8,3133.2 3215.4,3126.3 3214.2,3119.6 3212.2,3113 3209.5,3106.7 3206.1,3100.7 3202,3095.2 3197.2,3090.2 3192,3085.8 3186.2,3082 3180.1,3078.9 3173.6,3076.6 3167,3075 3160.1,3074.2 3153.3,3074.2 3146.5,3075 3139.8,3076.6 3133.3,3078.9 3127.2,3082 3121.4,3085.8 3116.2,3090.2 3111.5,3095.2 3107.4,3100.7 3103.9,3106.7 3101.2,3113 3099.2,3119.6 3098.1,3126.3 3097.7,3133.2 3098.1,3140 3099.2,3146.8 3101.2,3153.4 3103.9,3159.7 3107.4,3165.6 3111.5,3171.1 3116.2,3176.1 3121.4,3180.5 3127.2,3184.3 3133.3,3187.4 3139.8,3189.7 3146.5,3191.3 3153.3,3192.1 3160.1,3192.1 3167,3191.3 3173.6,3189.7 3180.1,3187.4 3186.2,3184.3 3192,3180.5 3197.2,3176.1 3202,3171.1 3206.1,3165.6 3209.5,3159.7 3212.2,3153.4 3214.2,3146.8 3215.4,3140
  region: 3215.8,3133.2 3215.4,3126.3 3214.2,3119.6 3212.2,3113 3209.5,3106.7 3206.1,3100.7 3202,3095.2 3197.2,3090.2 3192,3085.8 3186.2,3082 3180.1,3078.9 3173.6,3076.6 3167,3075 3160.1,3074.2 3153.3,3074.2 3146.5,3075 3139.8,3076.6 3133.3,3078.9 3127.2,3082 3121.4,3085.8 3116.2,3090.2 3111.5,3095.2 3107.4,3100.7 3103.9,3106.7 3101.2,3113 3099.2,3119.6 3098.1,3126.3 3097.7,3133.2 3098.1,3140 3099.2,3146.8 3101.2,3153.4 3103.9,3159.7 3107.4,3165.6 3111.5,3171.1 3116.2,3176.1 3121.4,3180.5 3127.2,3184.3 3133.3,3187.4 3139.8,3189.7 3146.5,3191.3 3153.3,3192.1 3160.1,3192.1 3167,3191.3 3173.6,3189.7 3180.1,3187.4 3186.2,3184.3 3192,3180.5 3197.2,3176.1 3202,3171.1 3206.1,3165.6 3209.5,3159.7 3212.2,3153.4 3214.2,3146.8 3215.4,3140
  lines w0.1: 3097.7,3133.2 3098.1,3126.3 3099.2,3119.6 3101.2,3113 3103.9,3106.7 3107.4,3100.7 3111.5,3095.2 3116.2,3090.2 3121.4,3085.8 3127.2,3082 3133.3,3078.9 3139.8,3076.6 3146.5,3075 3153.3,3074.2 3160.1,3074.2 3167,3075 3173.6,3076.6 3180.1,3078.9 3186.2,3082 3192,3085.8 3197.2,3090.2 3202,3095.2 3206.1,3100.7 3209.5,3106.7 3212.2,3113 3214.2,3119.6 3215.4,3126.3 3215.8,3133.2 3215.4,3140 3214.2,3146.8 3212.2,3153.4 3209.5,3159.7 3206.1,3165.6 3202,3171.1 3197.2,3176.1 3192,3180.5 3186.2,3184.3 3180.1,3187.4 3173.6,3189.7 3167,3191.3 3160.1,3192.1 3153.3,3192.1 3146.5,3191.3 3139.8,3189.7 3133.3,3187.4 3127.2,3184.3 3121.4,3180.5 3116.2,3176.1 3111.5,3171.1 3107.4,3165.6 3103.9,3159.7 3101.2,3153.4 3099.2,3146.8 3098.1,3140 3097.7,3133.2 ; 3097.7,6046.6 3098.1,6039.7 3099.2,6032.9 3101.2,6026.4 3103.9,6020.1 3107.4,6014.1 3111.5,6008.6 3116.2,6003.6 3121.4,5999.2 3127.2,5995.4 3133.3,5992.3 3139.8,5990 3146.5,5988.4 3153.3,5987.6 3160.1,5987.6 3167,5988.4 3173.6,5990 3180.1,5992.3 3186.2,5995.4 3192,5999.2 3197.2,6003.6 3202,6008.6 3206.1,6014.1 3209.5,6020.1 3212.2,6026.4 3214.2,6032.9 3215.4,6039.7 3215.8,6046.6 3215.4,6053.4 3214.2,6060.2 3212.2,6066.8 3209.5,6073.1 3206.1,6079 3202,6084.5 3197.2,6089.5 3192,6093.9 3186.2,6097.7 3180.1,6100.8 3173.6,6103.1 3167,6104.7 3160.1,6105.5 3153.3,6105.5 3146.5,6104.7 3139.8,6103.1 3133.3,6100.8 3127.2,6097.7 3121.4,6093.9 3116.2,6089.5 3111.5,6084.5 3107.4,6079 3103.9,6073.1 3101.2,6066.8 3099.2,6060.2 3098.1,6053.4 3097.7,6046.6 ; 6601.6,3133.2 6602,3126.3 6603.2,3119.6 6605.2,3113 6607.9,3106.7 6611.3,3100.7 6615.4,3095.2 6620.1,3090.2 6625.4,3085.8 6631.1,3082 6637.3,3078.9 6643.7,3076.6 6650.4,3075 6657.2,3074.2 6664.1,3074.2 6670.9,3075 6677.6,3076.6 6684,3078.9 6690.2,3082 6695.9,3085.8 6701.2,3090.2 6705.9,3095.2 6710,3100.7 6713.4,3106.7 6716.1,3113 6718.1,3119.6 6719.3,3126.3 6719.7,3133.2 6719.3,3140 6718.1,3146.8 6716.1,3153.4 6713.4,3159.7 6710,3165.6 6705.9,3171.1 6701.2,3176.1 6695.9,3180.5 6690.2,3184.3 6684,3187.4 6677.6,3189.7 6670.9,3191.3 6664.1,3192.1 6657.2,3192.1 6650.4,3191.3 6643.7,3189.7 6637.3,3187.4 6631.1,3184.3 6625.4,3180.5 6620.1,3176.1 6615.4,3171.1 6611.3,3165.6 6607.9,3159.7 6605.2,3153.4 6603.2,3146.8 6602,3140 6601.6,3133.2 ; 6601.6,6046.6 6602,6039.7 6603.2,6032.9 6605.2,6026.4 6607.9,6020.1 6611.3,6014.1 6615.4,6008.6 6620.1,6003.6 6625.4,5999.2 6631.1,5995.4 6637.3,5992.3 6643.7,5990 6650.4,5988.4 6657.2,5987.6 6664.1,5987.6 6670.9,5988.4 6677.6,5990 6684,5992.3 6690.2,5995.4 6695.9,5999.2 6701.2,6003.6 6705.9,6008.6 6710,6014.1 6713.4,6020.1 6716.1,6026.4 6718.1,6032.9 6719.3,6039.7 6719.7,6046.6 6719.3,6053.4 6718.1,6060.2 6716.1,6066.8 6713.4,6073.1 6710,6079 6705.9,6084.5 6701.2,6089.5 6695.9,6093.9 6690.2,6097.7 6684,6100.8 6677.6,6103.1 6670.9,6104.7 6664.1,6105.5 6657.2,6105.5 6650.4,6104.7 6643.7,6103.1 6637.3,6100.8 6631.1,6097.7 6625.4,6093.9 6620.1,6089.5 6615.4,6084.5 6611.3,6079 6607.9,6073.1 6605.2,6066.8 6603.2,6060.2 6602,6053.4 6601.6,6046.6
  lines w10: 3038.6,3015.1 3038.6,6164.7 6778.8,6164.7 6778.8,3015.1 3038.6,3015.1

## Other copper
Top Layer:
  text "SSR+ GND NO NO" at 3063.6,5895.1 h39.4
  text "PWM GND 5V NO" at 3088.6,5565.1 h39.4
  text "Jump for  / board 5V" at 3063.6,5075.1 h39.4

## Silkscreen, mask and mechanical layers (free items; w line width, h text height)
Top Silkscreen Layer:
  drawing of 69 lines, arcs and shapes, not listed
  text "ET Type K" at 3038.6,4715.1 h118.1
  text "BT Type K" at 3051.6,3991.2 h118.1
  text "Crack ESP" at 5458.6,3608.6 h120
  text "Main ESP" at 4203.6,3605.1 h120
  text "GND D VCC NO" at 3323.6,3050.1 h39.4
  text "GND DA SC VCC" at 3888.6,3050.1 h39.4
  text "GND DA SC VCC" at 4408.6,3050.1 h39.4
  text "GND D VCC NO" at 4943.6,3050.1 h39.4
  text "GND D VCC NO" at 5823.6,3050.1 h39.4
Mechanical Layer:
  drawing of 216 lines, arcs and shapes, not listed
Mech36:
  region: 6164.3,3135.1 6163.9,3131 6162.7,3127.2 6160.8,3123.6 6158.2,3120.4 6155.1,3117.9 6151.5,3116 6147.6,3114.8 6143.6,3114.4 6139.6,3114.8 6135.7,3116 6132.1,3117.9 6129,3120.4 6126.4,3123.6 6124.5,3127.2 6123.3,3131 6122.9,3135.1 6123.3,3139.1 6124.5,3143 6126.4,3146.5 6129,3149.7 6132.1,3152.2 6135.7,3154.2 6139.6,3155.3 6143.6,3155.7 6147.6,3155.3 6151.5,3154.2 6155.1,3152.2 6158.2,3149.7 6160.8,3146.5 6162.7,3143 6163.9,3139.1
  region: 3159.3,6065.1 3158.9,6061 3157.7,6057.2 3155.8,6053.6 3153.2,6050.4 3150.1,6047.9 3146.5,6046 3142.6,6044.8 3138.6,6044.4 3134.6,6044.8 3130.7,6046 3127.1,6047.9 3124,6050.4 3121.4,6053.6 3119.5,6057.2 3118.3,6061 3117.9,6065.1 3118.3,6069.1 3119.5,6073 3121.4,6076.5 3124,6079.7 3127.1,6082.2 3130.7,6084.2 3134.6,6085.3 3138.6,6085.7 3142.6,6085.3 3146.5,6084.2 3150.1,6082.2 3153.2,6079.7 3155.8,6076.5 3157.7,6073 3158.9,6069.1
  region: 6109.3,6065.1 6108.9,6061 6107.7,6057.2 6105.8,6053.6 6103.2,6050.4 6100.1,6047.9 6096.5,6046 6092.6,6044.8 6088.6,6044.4 6084.6,6044.8 6080.7,6046 6077.1,6047.9 6074,6050.4 6071.4,6053.6 6069.5,6057.2 6068.3,6061 6067.9,6065.1 6068.3,6069.1 6069.5,6073 6071.4,6076.5 6074,6079.7 6077.1,6082.2 6080.7,6084.2 6084.6,6085.3 6088.6,6085.7 6092.6,6085.3 6096.5,6084.2 6100.1,6082.2 6103.2,6079.7 6105.8,6076.5 6107.7,6073 6108.9,6069.1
